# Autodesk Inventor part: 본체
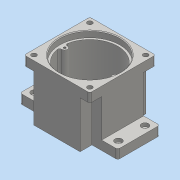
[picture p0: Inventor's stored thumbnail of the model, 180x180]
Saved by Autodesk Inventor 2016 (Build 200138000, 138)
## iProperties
Created: 2020-08
Part Number: 본체
Material: 일반
Document SubType Name: Modeling
Designer: User
Density: 1 g/cm^3
Appearance: 기본값
Author: User
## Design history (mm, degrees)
sketch "스케치1"
  geometry: L1 (33, 47)-(-33, 47); L2 (-33, 47)-(-33, -47); L3 (-33, -47)-(33, -47); L4 (33, -47)-(33, 47); L5 (33, 47)-(-33, -47); L6 (-33, 47)-(33, -47); L7 (-70, 30)-(70, 30); L8 (70, 30)-(70, -30); L9 (70, -30)-(-70, -30); L10 (-70, -30)-(-70, 30); L11 (-70, 30)-(70, -30); L12 (70, 30)-(-70, -30); 1 further point
  constraints: 24 end point, 4 midpoint, 4 parallel, 2 horizontal, 2 perpendicular
  dimensions: "d0" = 66 distance of L3.end L2.end; "d1" = 94 distance of L2.end L1.end; "d2" = 140 distance of L8.end L9.end; "d3" = 60 distance of L7.end L8.end
extrude "돌출1" new body sketch "스케치1" distance "d4" = 13; taper "d5" = 0 deg
sketch "스케치2"
  geometry: L1 (-47, 47)-(47, 47); L2 (47, 47)-(47, -47); L3 (47, -47)-(-47, -47); L4 (-47, -47)-(-47, 47); L5 (-47, 47)-(47, -47); L6 (47, 47)-(-47, -47); 1 further point
  constraints: 12 end point, 2 midpoint, 2 parallel, 1 horizontal, 1 perpendicular
  dimensions: "d6" = 94 distance of L2.end L3.end; "d7" = 94 distance of L1.end L2.end
extrude "돌출2" join sketch "스케치2" distance "d8" = 67; taper "d9" = 0 deg
sketch "스케치3"
  geometry: L1 (33, 30)-(47, 30) reference; L2 (47, 30)-(47, 47) reference; L3 (47, 47)-(33, 47) reference; L4 (33, 47)-(33, 30) reference; L5 (-47, 30)-(-33, 30) reference; L6 (-33, 30)-(-33, 47) reference; L7 (-33, 47)-(-47, 47) reference; L8 (-47, 47)-(-47, 30) reference; L9 (-33, -47)-(-33, -30) reference; L10 (-33, -30)-(-47, -30) reference; L11 (-47, -30)-(-47, -47) reference; L12 (-47, -47)-(-33, -47) reference; L13 (33, -30)-(33, -47) reference; L14 (33, -47)-(47, -47) reference; L15 (47, -47)-(47, -30) reference; L16 (47, -30)-(33, -30) reference; 1 further point
extrude "돌출3" cut sketch "스케치3" distance "d10" = 54; taper "d11" = 0 deg
sketch "스케치4"
  geometry: C1 r 27.5 at (0, 11); 1 further point
  constraints: 1 centre point, 1 vertical alignment
  dimensions: "d12" = 55 diameter of C1; "d13" = 11 distance of point (0, 0) C1.centre
extrude "돌출4" join sketch "스케치4" distance "d14" = 7; taper "d15" = 0 deg
sketch "스케치5"
  geometry: C1 r 43 at (0, 0); 1 further point
  constraints: 1 centre point, 1 coincident
  dimensions: "d16" = 86 diameter of C1
extrude "돌출5" cut sketch "스케치5" distance "d17" = 9; taper "d18" = 0 deg
sketch "스케치6"
  geometry: C1 r 40 at (0, 0); 1 further point
  constraints: 1 centre point, 1 coincident
  dimensions: "d19" = 80 diameter of C1
extrude "돌출6" cut sketch "스케치6" distance "d20" = 62; taper "d21" = 0 deg
sketch "스케치7"
  geometry: C1 r 27.5 at (0, 11) reference; C2 r 21 at (0, 11); C3 r 15 at (0, -20); 1 further point
  constraints: 2 centre point, 1 coincident, 1 vertical alignment
  dimensions: "d22" = 42 diameter of C2; "d23" = 30 diameter of C3; "d24" = 20 distance of C3.centre point (0, 0)
extrude "돌출7" join sketch "스케치7" distance "d25" = 7; taper "d26" = 0 deg
sketch "스케치8"
  geometry: C1 r 17.5 at (0, 11); A1 r 21 centre (0, 11) between (8.978, -7.984) and (-8.978, -7.984) reference; 1 further point
  constraints: 1 centre point, 1 coincident
  dimensions: "d27" = 35 diameter of C1
extrude "돌출8" cut sketch "스케치8" distance "d28" = 10; taper "d29" = 0 deg
sketch "스케치9"
  geometry: C1 r 11 at (0, -20); A1 r 15 centre (0, -20) between (-8.978, -7.984) and (8.978, -7.984) reference; 1 further point
  constraints: 1 centre point, 1 coincident
  dimensions: "d30" = 22 diameter of C1
extrude "돌출9" cut sketch "스케치9" distance "d31" = 7; taper "d32" = 0 deg
sketch "스케치10"
  geometry: C1 r 11 at (0, 0) reference; C2 r 9.5 at (0, 0); 1 further point
  constraints: 1 centre point, 1 coincident
  dimensions: "d33" = 19 diameter of C2
extrude "돌출10" cut sketch "스케치10" distance "d34" = 3; taper "d35" = 0 deg
sketch "스케치11"
  geometry: C1 r 27.5 at (0, 0) reference; C2 r 16 at (0, 0); 1 further point
  constraints: 1 centre point, 1 coincident
  dimensions: "d36" = 32 diameter of C2
extrude "돌출11" cut sketch "스케치11" distance "d37" = 8.3; taper "d38" = 0 deg
sketch "스케치12"
  geometry: C1 r 16 at (0, 0) reference; C2 r 12.5 at (0, 0); 1 further point
  constraints: 1 centre point, 1 coincident
  dimensions: "d39" = 25 diameter of C2
extrude "돌출12" cut sketch "스케치12" distance "d40" = 8; taper "d41" = 0 deg
sketch "스케치13"
  geometry: A1 r 4 centre (36, 0) between (36.19, 3.995) and (36.19, -3.995); A2 r 3 centre (36.333, 6.992) between (36.19, 3.995) and (39.279, 7.559); A3 r 3 centre (36.333, -6.992) between (39.279, -7.559) and (36.19, -3.995); A4 r 40 centre (0, 0) between (39.279, 7.559) and (39.279, -7.559) reference; 1 further point
  constraints: 8 point on circle, 5 tangent, 3 centre point, 1 horizontal alignment
  dimensions: "d42" = 8 diameter of A1; "d44" = 6 diameter of A2; "d45" = 6 diameter of A3
extrude "돌출13" join sketch "스케치13" stored distance "d46" = 8; taper "d47" = 0 deg
hole "구멍1" diameter "d50" = 3.242; stored, may be unused: countersink angle "d54" = 90 deg, drill point angle "d56" = 118 deg; dims "d48" = 10, "d49" = 10, "d51" = 7, "d52" = 4, "d53" = 2, "d55" = 9
sketch "스케치14"
  geometry: L1 (66, 0)-(0, 0) reference; L2 (80, -80)-(-14, -80) reference; 3 further points
  constraints: 1 midpoint, 1 vertical alignment, 1 other
  dimensions: "d57" = 40 distance from line of point (33, -40) L2
feature "엠보싱1" sketch "스케치14" dims "d0" = 66, "d1" = 94, "d58" = 0.5, "d59" = 0
sketch "스케치15"
  geometry: L1 (47, 47)-(-47, 47) reference; L2 (47, -47)-(47, 47) reference; C1 r 3.5 at (40, 40); 1 further point
  constraints: 1 centre point
  dimensions: "d60" = 7 diameter of C1; "d61" = 7 distance from line of L1 C1.centre; "d62" = 7 distance from line of C1.centre L2
extrude "돌출14" cut sketch "스케치15" distance "d63" = 20; taper "d64" = 0 deg
sketch "스케치16"
  geometry: L1 (-47, 30)-(-70, 30) reference; L2 (-70, 30)-(-70, -30) reference; C1 r 5 at (-60, 19); 1 further point
  constraints: 1 centre point
  dimensions: "d71" = 10 diameter of C1; "d72" = 11 distance from line of C1.centre L1; "d73" = 10 distance from line of C1.centre L2
extrude "돌출15" cut sketch "스케치16" distance "d74" = 5; taper "d75" = 0 deg
sketch "스케치17"
  geometry: C1 r 5 at (0, 0) reference; C2 r 2.25 at (0, 0); 1 further point
  constraints: 1 centre point, 1 coincident
  dimensions: "d76" = 4.5 diameter of C2
extrude "돌출16" cut sketch "스케치17" distance "d77" = 10; taper "d78" = 0 deg
fillet "모깎기1" dims "d85" = 3
fillet "모깎기2" dims "d86" = 3
chamfer "모따기1" distance "d87" = 1; stored, may be unused: second distance "d88" = 2, angle "d89" = 45 deg
chamfer "모따기2" distance "d90" = 0.8; stored, may be unused: second distance "d91" = 2, angle "d92" = 30 deg
node "솔리드1"
mirror "대칭1"
pattern_linear "직사각형 패턴1" dims "d67" = 80
pattern_linear "직사각형 패턴2" dims "d84" = 38
node "투영된 루프1"
node "투영된 루프2"
node "투영된 루프3"
node "투영된 루프4"
